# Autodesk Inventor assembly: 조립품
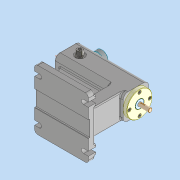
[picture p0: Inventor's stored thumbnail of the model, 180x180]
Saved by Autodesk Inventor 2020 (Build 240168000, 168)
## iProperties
Created: 2024-07
Part Number: 조립품
Document SubType Name: Assembly
Designer: oem
Author: oem
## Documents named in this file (12)
- C:\Users\oem\Desktop\740704V1010\조립품.iam
- C:\Users\oem\Desktop\740704V1010\본체.ipt
- C:\Users\oem\Desktop\740704V1010\부시.ipt
- C:\Users\oem\Desktop\740704V1010\슬리브.ipt
- C:\Users\oem\Desktop\740704V1010\나사축.ipt
- C:\Users\oem\Desktop\740704V1010\스러스트 볼 베어링 51101.ipt
- C:\Users\oem\Desktop\740704V1010\센터.ipt
- C:\Users\oem\Desktop\740704V1010\스톱퍼.ipt
- C:\Users\oem\Desktop\740704V1010\육각 소켓 머리 볼트 M6x12.ipt
- C:\Users\oem\Desktop\740704V1010\육각 소켓 머리 볼트 M12x16.ipt
- C:\Users\oem\Desktop\740704V1010\스프링  와셔 M12.ipt
- C:\Users\oem\Desktop\740704V1010\평와셔 M12.ipt
